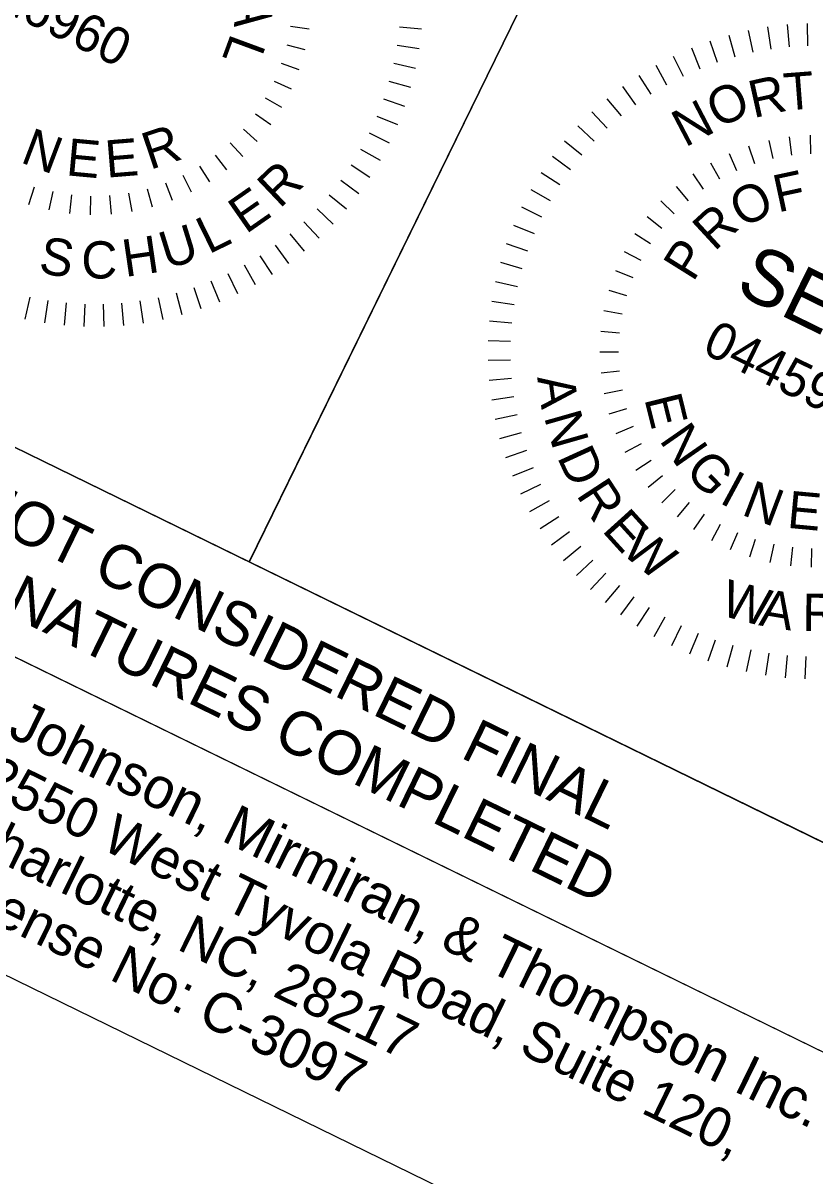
# Model space of a CAD drawing. Extents: x 1518247 to 1523638, y 635234 to 639927.
# Drawn here: x 1521266.7 to 1521365.4, y 636051.2 to 636194.9 of the extents above; entities that cross this region are included whole.
import ezdxf

# ---------------------------------------------------------------- set-up
doc = ezdxf.new("R2010")
doc.units = 0
for name, color, linetype in [('Default', 7, 'Continuous'), ('DTM TIN Hull White', 7, 'Continuous'), ('Sheet Sticker Exception Certification CELL', 7, 'Continuous'), ('Sheet Typical CELL', 7, 'Continuous')]:
    doc.layers.add(name, color=color, linetype=linetype)

msp = doc.modelspace()

# ---------------------------------------------------------------- linework, layer by layer
at = {"layer": 'Default'}
msp.add_lwpolyline([(1521178.87, 636118.13), (1521358.57, 636030.25), (1521374.43, 636062.67), (1521194.73, 636150.56)], close=True, dxfattribs=at)
at = {"layer": 'DTM TIN Hull White'}
for p, q in [((1521302.39, 636194.12), (1521300.09, 636194.46)), ((1521361.98, 636194.7), (1521362.23, 636191.93)), ((1521364.45, 636194.84), (1521364.52, 636192.06)), ((1521316.42, 636194.12), (1521313.64, 636194.38)), ((1521354.7, 636193.38), (1521355.44, 636190.7)), ((1521357.1, 636193.97), (1521357.68, 636191.25)), ((1521359.53, 636194.41), (1521359.94, 636191.65)), ((1521301.9, 636191.57), (1521299.64, 636192.12)), ((1521316.11, 636191.67), (1521313.36, 636192.1)), ((1521350.03, 636191.79), (1521351.09, 636189.21)), ((1521352.34, 636192.66), (1521353.24, 636190.02)), ((1521347.77, 636190.78), (1521348.99, 636188.27)), ((1521301.16, 636189.07), (1521298.97, 636189.84)), ((1521315.66, 636189.24), (1521312.94, 636189.84)), ((1521345.59, 636189.64), (1521346.95, 636187.21)), ((1521300.19, 636186.66), (1521298.08, 636187.63)), ((1521315.06, 636186.85), (1521312.38, 636187.6)), ((1521343.47, 636188.37), (1521344.98, 636186.02)), ((1521341.43, 636186.97), (1521343.08, 636184.72)), ((1521298.99, 636184.35), (1521296.98, 636185.52)), ((1521314.32, 636184.49), (1521311.69, 636185.41)), ((1521339.49, 636185.45), (1521341.27, 636183.31)), ((1521295.73, 636183.59), (1521297.62, 636182.24)), ((1521313.44, 636182.19), (1521310.87, 636183.26)), ((1521337.63, 636183.82), (1521339.54, 636181.78)), ((1521295.94, 636180.13), (1521294.2, 636181.66)), ((1521335.88, 636182.08), (1521337.91, 636180.17)), ((1521312.42, 636179.94), (1521309.92, 636181.16)), ((1521334.24, 636180.23), (1521336.38, 636178.45)), ((1521359.67, 636180.27), (1521360.18, 636178)), ((1521362.23, 636180.72), (1521362.52, 636178.41)), ((1521364.83, 636180.91), (1521364.89, 636178.59)), ((1521294.13, 636178.26), (1521292.54, 636179.95)), ((1521311.27, 636177.75), (1521308.84, 636179.13)), ((1521354.73, 636178.64), (1521355.66, 636176.52)), ((1521357.16, 636179.57), (1521357.89, 636177.37)), ((1521292.15, 636176.58), (1521290.73, 636178.42)), ((1521332.71, 636178.3), (1521334.95, 636176.64)), ((1521352.4, 636177.49), (1521353.53, 636175.46)), ((1521287.74, 636173.82), (1521286.7, 636175.9)), ((1521290.01, 636175.09), (1521288.78, 636177.06)), ((1521309.98, 636175.64), (1521307.65, 636177.16)), ((1521331.31, 636176.27), (1521333.64, 636174.75)), ((1521350.2, 636176.1), (1521351.52, 636174.19)), ((1521267.48, 636172.28), (1521268.19, 636174.49)), ((1521285.36, 636172.77), (1521284.53, 636174.94)), ((1521308.58, 636173.61), (1521306.34, 636175.27)), ((1521348.13, 636174.51), (1521349.63, 636172.75)), ((1521269.99, 636171.6), (1521270.49, 636173.88)), ((1521272.56, 636171.17), (1521272.83, 636173.48)), ((1521275.16, 636171), (1521275.21, 636173.32)), ((1521277.76, 636171.07), (1521277.58, 636173.38)), ((1521280.34, 636171.39), (1521279.94, 636173.67)), ((1521282.89, 636171.96), (1521282.27, 636174.2)), ((1521307.05, 636171.68), (1521304.91, 636173.46)), ((1521330.02, 636174.16), (1521332.45, 636172.79)), ((1521305.41, 636169.83), (1521303.38, 636171.75)), ((1521328.87, 636171.97), (1521331.37, 636170.75)), ((1521346.23, 636172.73), (1521347.9, 636171.12)), ((1521303.66, 636168.09), (1521301.75, 636170.13)), ((1521344.51, 636170.78), (1521346.33, 636169.33)), ((1521301.8, 636166.46), (1521300.02, 636168.6)), ((1521327.85, 636169.72), (1521330.42, 636168.65)), ((1521342.99, 636168.67), (1521344.93, 636167.41)), ((1521299.86, 636164.94), (1521298.21, 636167.19)), ((1521326.97, 636167.42), (1521329.6, 636166.5)), ((1521297.82, 636163.54), (1521296.31, 636165.89)), ((1521341.67, 636166.42), (1521343.73, 636165.35)), ((1521295.7, 636162.27), (1521294.34, 636164.7)), ((1521326.23, 636165.07), (1521328.91, 636164.31)), ((1521293.51, 636161.13), (1521292.3, 636163.64)), ((1521340.59, 636164.06), (1521342.74, 636163.19)), ((1521288.95, 636159.25), (1521288.05, 636161.89)), ((1521291.26, 636160.12), (1521290.2, 636162.7)), ((1521325.63, 636162.67), (1521328.35, 636162.07)), ((1521339.73, 636161.6), (1521341.96, 636160.94)), ((1521267.03, 636157.99), (1521267.63, 636160.71)), ((1521269.46, 636157.53), (1521269.89, 636160.29)), ((1521271.91, 636157.23), (1521272.17, 636160.01)), ((1521279.31, 636157.21), (1521279.06, 636159.99)), ((1521281.76, 636157.5), (1521281.35, 636160.26)), ((1521284.19, 636157.94), (1521283.61, 636160.66)), ((1521286.59, 636158.53), (1521285.85, 636161.21)), ((1521325.18, 636160.24), (1521327.93, 636159.81)), ((1521274.37, 636157.08), (1521274.47, 636159.86)), ((1521276.84, 636157.07), (1521276.77, 636159.85)), ((1521339.11, 636159.07), (1521341.39, 636158.63)), ((1521324.87, 636157.79), (1521327.65, 636157.53)), ((1521338.75, 636156.49), (1521341.06, 636156.27)), ((1521324.72, 636155.33), (1521327.5, 636155.23)), ((1521324.71, 636152.86), (1521327.5, 636152.93)), ((1521338.63, 636153.89), (1521340.95, 636153.9)), ((1521338.77, 636151.3), (1521341.08, 636151.52)), ((1521324.85, 636150.39), (1521327.63, 636150.64)), ((1521339.15, 636148.72), (1521341.43, 636149.17)), ((1521325.15, 636147.94), (1521327.9, 636148.35)), ((1521325.58, 636145.51), (1521328.31, 636146.09)), ((1521339.78, 636146.19), (1521342, 636146.86)), ((1521340.65, 636143.74), (1521342.8, 636144.62)), ((1521326.17, 636143.11), (1521328.85, 636143.85)), ((1521326.9, 636140.75), (1521329.53, 636141.65)), ((1521341.76, 636141.38), (1521343.81, 636142.47)), ((1521343.09, 636139.14), (1521345.03, 636140.42)), ((1521327.77, 636138.44), (1521330.34, 636139.5)), ((1521344.63, 636137.04), (1521346.43, 636138.5)), ((1521328.78, 636136.19), (1521331.28, 636137.4)), ((1521346.36, 636135.1), (1521348.02, 636136.73)), ((1521329.91, 636134), (1521332.34, 636135.36)), ((1521349.75, 636135.12), (1521348.25, 636133.34)), ((1521331.18, 636131.88), (1521333.53, 636133.39)), ((1521350.34, 636131.76), (1521351.65, 636133.67)), ((1521332.58, 636129.84), (1521334.83, 636131.49)), ((1521352.56, 636130.39), (1521353.68, 636132.43)), ((1521354.89, 636129.25), (1521355.82, 636131.38)), ((1521357.33, 636128.33), (1521358.04, 636130.54)), ((1521359.85, 636127.66), (1521360.34, 636129.93)), ((1521334.1, 636127.9), (1521336.25, 636129.68)), ((1521362.41, 636127.23), (1521362.68, 636129.54)), ((1521365.01, 636127.05), (1521365.06, 636129.37)), ((1521335.73, 636126.04), (1521337.77, 636127.95)), ((1521337.47, 636124.29), (1521339.39, 636126.32)), ((1521339.32, 636122.65), (1521341.11, 636124.79)), ((1521341.26, 636121.12), (1521342.91, 636123.36)), ((1521343.29, 636119.72), (1521344.8, 636122.05)), ((1521345.4, 636118.43), (1521346.77, 636120.86)), ((1521347.58, 636117.28), (1521348.81, 636119.78)), ((1521349.83, 636116.26), (1521350.9, 636118.83)), ((1521352.14, 636115.38), (1521353.05, 636118.01)), ((1521354.49, 636114.64), (1521355.25, 636117.32)), ((1521356.88, 636114.04), (1521357.48, 636116.76)), ((1521359.31, 636113.59), (1521359.74, 636116.34)), ((1521361.76, 636113.28), (1521362.02, 636116.06)), ((1521364.23, 636113.13), (1521364.32, 636115.91))]:
    msp.add_line(p, q, dxfattribs=at)
at = {"layer": 'Sheet Sticker Exception Certification CELL'}
for p, q in [((1521205.05, 636171.67), (1521384.75, 636083.78)), ((1521374.43, 636062.67), (1521194.73, 636150.56))]:
    msp.add_line(p, q, dxfattribs=at)
at = {"layer": 'Sheet Typical CELL'}
msp.add_line((1521344.36, 636228.77), (1521294.95, 636127.76), dxfattribs=at)
for points in [[(1521254.48, 636272.73), (1521344.36, 636228.77), (1521294.93, 636127.71), (1521205.05, 636171.67)], [(1521344.36, 636228.77), (1521434.19, 636184.84), (1521384.76, 636083.78), (1521294.93, 636127.71)]]:
    msp.add_lwpolyline(points, close=True, dxfattribs=at)

# ---------------------------------------------------------------- texts
at = {"layer": 'Default'}
for s, height, p in [('Johnson, Mirmiran, & Thompson Inc.', 5.1112, (1521264.67, 636106.06)), ('2550 West Tyvola Road, Suite 120,', 4.9652, (1521261.38, 636099.32)), ('Charlotte, NC, 28217', 4.9652, (1521258.26, 636092.95)), ('License No: C-3097', 4.9652, (1521255.14, 636086.58))]:
    msp.add_text(s, height=height, rotation=333.9377, dxfattribs=at).set_placement(p)
at = {"layer": 'DTM TIN Hull White'}
for s, height, rotation, p in [('26960', 4.64, 333.8847, (1521263.19, 636196.89)), ('A', 4.64, 265.0516, (1521293.38, 636198.52)), ('L', 4.64, 249.7554, (1521292.71, 636193.74)), ('T', 4.64, 4.3843, (1521361.7, 636183.98)), ('O', 4.64, 25.602, (1521353.36, 636181.7)), ('R', 4.64, 12.5453, (1521357.76, 636183.03)), ('N', 4.64, 27.5614, (1521349.24, 636179.35)), ('N', 4.64, 339.3006, (1521266.28, 636177.58)), ('R', 4.64, 18.4496, (1521282.56, 636176.57)), ('E', 4.64, 354.6926, (1521272.02, 636175.93)), ('E', 4.64, 4.6785, (1521277.16, 636175.61)), ('R', 4.64, 43.5571, (1521298.72, 636171.68)), ('F', 4.64, 12.1253, (1521360.8, 636171.27)), ('E', 4.64, 34.8844, (1521294.51, 636168.52)), ('O', 4.64, 27.4216, (1521356.38, 636169.27)), ('R', 4.64, 42.7178, (1521352.9, 636166.34)), ('L', 4.64, 26.0918, (1521289.88, 636166.03)), ('U', 4.64, 17.2091, (1521284.64, 636164.18)), ('S', 4.64, 350.5013, (1521268.56, 636163.77)), ('C', 4.64, 359.5039, (1521273.99, 636163.07)), ('H', 4.64, 8.3265, (1521279.47, 636163.23)), ('P', 4.64, 58.0141, (1521350.24, 636162.52)), ('SEAL', 6.965, 333.8847, (1521355.29, 636161.35)), ('044590', 4.64, 333.8847, (1521351.2, 636153.85)), ('A', 4.64, 277.8197, (1521330.81, 636150.73)), ('E', 4.64, 283.9548, (1521344.15, 636148.07)), ('N', 4.64, 285.8915, (1521331.64, 636145.81)), ('N', 4.64, 304.8099, (1521345.95, 636142.88)), ('D', 4.64, 294.5343, (1521333.25, 636140.8)), ('G', 4.64, 313.5761, (1521349.07, 636138.93)), ('I', 4.64, 331.6709, (1521353.38, 636135.16)), ('R', 4.64, 303.2069, (1521335.61, 636136.08)), ('N', 4.64, 339.3006, (1521356.14, 636133.64)), ('E', 4.64, 354.6926, (1521361.87, 636131.98)), ('E', 4.64, 312.1794, (1521338.78, 636131.61)), ('W', 4.64, 321.0521, (1521341.11, 636128.91)), ('W', 4.64, 345.1793, (1521353.49, 636121.1)), ('A', 4.64, 350.5013, (1521358.34, 636119.83)), ('R', 4.64, 359.5039, (1521363.84, 636119.12))]:
    msp.add_text(s, height=height, rotation=rotation, dxfattribs=at).set_placement(p)
at = {"layer": 'Sheet Sticker Exception Certification CELL'}
for s, p in [('DOCUMENT NOT CONSIDERED FINAL', (1521219.44, 636153.12)), ('UNLESS ALL SIGNATURES COMPLETED', (1521211.02, 636147.44))]:
    msp.add_text(s, height=5.5, rotation=333.9377, dxfattribs=at).set_placement(p)
at = {"layer": 'Sheet Typical CELL'}
msp.add_text('PAVEMENT DESIGN', height=5.0001, rotation=333.9377, dxfattribs=at).set_placement((1521359.01, 636213.32))

doc.saveas('drawing.dxf')
